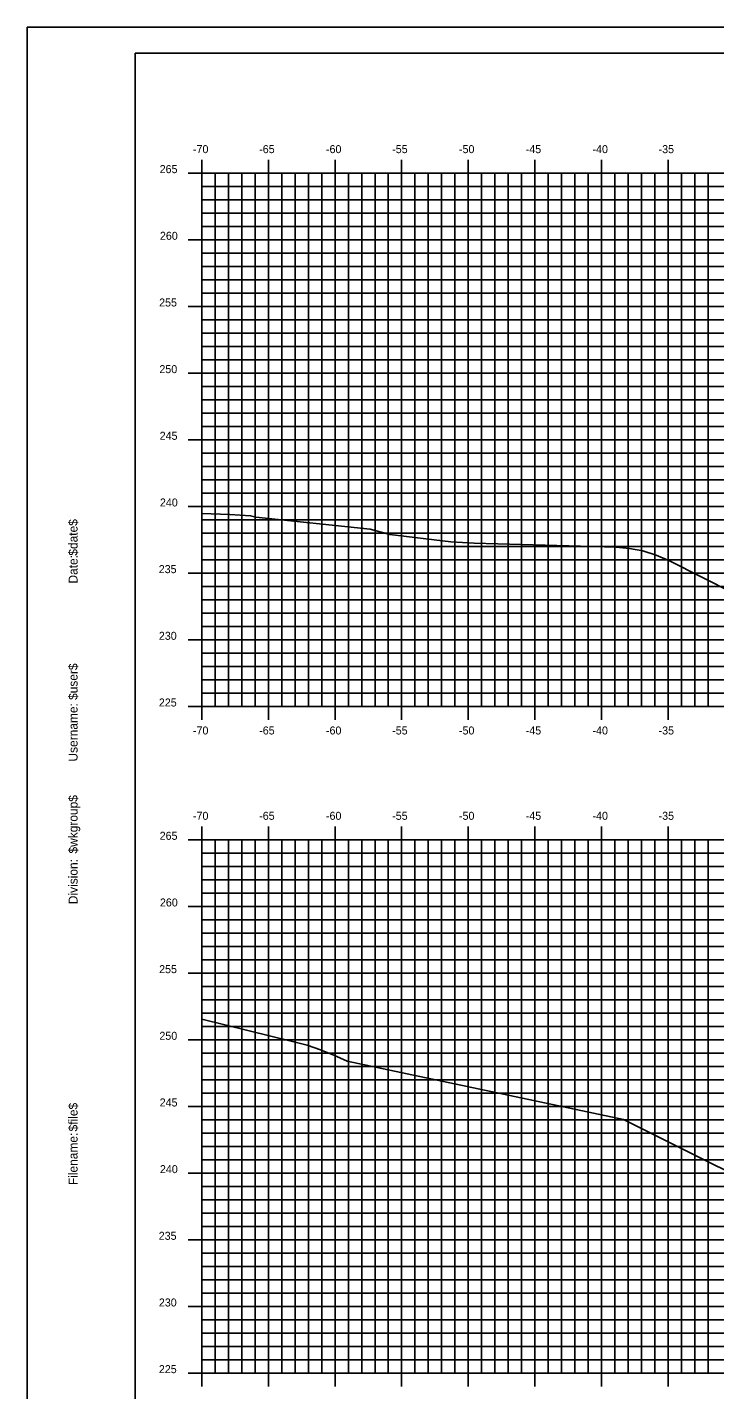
# Model space of a CAD drawing. Extents: x 1168600 to 1177589, y 610178 to 611246.
# Drawn here: x 1174091.5 to 1174143.1, y 610276.6 to 610378.7 of the extents above; entities that cross this region are included whole.
import ezdxf

# ---------------------------------------------------------------- set-up
doc = ezdxf.new("R2010")
doc.units = 0
for name, color, linetype in [('_Station Equation', 7, 'Continuous'), ('BORDER', 7, 'Continuous'), ('H_V ANNOTATION', 7, 'Continuous'), ('MAJOR', 7, 'Continuous'), ('MINOR', 7, 'Continuous'), ('PLOT BOUNDARY', 7, 'Continuous')]:
    doc.layers.add(name, color=color, linetype=linetype)

msp = doc.modelspace()

# ---------------------------------------------------------------- linework, layer by layer
at = {"layer": '_Station Equation'}
for points in [[(1174104.58, 610342.27), (1174106.68, 610342.2), (1174108.24, 610342.1), (1174108.63, 610342), (1174117.22, 610341.1), (1174118.7, 610340.71), (1174123.26, 610340.14), (1174125.03, 610340.05), (1174135.67, 610339.74), (1174135.67, 610339.74), (1174135.67, 610339.74), (1174136.67, 610339.66), (1174137.67, 610339.47), (1174138.67, 610339.15), (1174139.67, 610338.72), (1174139.67, 610338.72), (1174144.49, 610336.31), (1174144.49, 610336.31)], [(1174104.58, 610304.35), (1174111.49, 610302.66), (1174111.49, 610302.66), (1174111.49, 610302.66), (1174112.49, 610302.39), (1174113.49, 610302.06), (1174114.49, 610301.66), (1174115.49, 610301.19), (1174136.23, 610296.83), (1174136.23, 610296.83), (1174136.23, 610296.83), (1174150.5, 610289.69)]]:
    msp.add_lwpolyline(points, dxfattribs=at)
at = {"layer": 'BORDER'}
for p, q in [((1174259.58, 610376.8), (1174099.58, 610376.8)), ((1174099.58, 610376.8), (1174099.58, 610271.8))]:
    msp.add_line(p, q, dxfattribs=at)
at = {"layer": 'MAJOR'}
for p, q in [((1174104.58, 610368.8), (1174104.58, 610367.8)), ((1174109.58, 610368.8), (1174109.58, 610367.8)), ((1174114.58, 610368.8), (1174114.58, 610367.8)), ((1174119.58, 610368.8), (1174119.58, 610367.8)), ((1174124.58, 610368.8), (1174124.58, 610367.8)), ((1174129.58, 610368.8), (1174129.58, 610367.8)), ((1174134.58, 610368.8), (1174134.58, 610367.8)), ((1174139.58, 610368.8), (1174139.58, 610367.8)), ((1174103.57, 610367.8), (1174104.58, 610367.8)), ((1174104.58, 610367.8), (1174244.58, 610367.8)), ((1174104.58, 610327.8), (1174104.58, 610367.8)), ((1174104.58, 610327.8), (1174104.58, 610367.8)), ((1174104.58, 610367.8), (1174244.58, 610367.8)), ((1174109.58, 610327.8), (1174109.58, 610367.8)), ((1174114.58, 610327.8), (1174114.58, 610367.8)), ((1174119.58, 610327.8), (1174119.58, 610367.8)), ((1174124.58, 610327.8), (1174124.58, 610367.8)), ((1174129.58, 610327.8), (1174129.58, 610367.8)), ((1174134.58, 610327.8), (1174134.58, 610367.8)), ((1174139.58, 610327.8), (1174139.58, 610367.8)), ((1174103.57, 610362.8), (1174104.58, 610362.8)), ((1174104.58, 610362.8), (1174244.58, 610362.8)), ((1174103.57, 610357.8), (1174104.58, 610357.8)), ((1174104.58, 610357.8), (1174244.58, 610357.8)), ((1174103.57, 610352.8), (1174104.58, 610352.8)), ((1174104.58, 610352.8), (1174244.58, 610352.8)), ((1174103.57, 610347.8), (1174104.58, 610347.8)), ((1174104.58, 610347.8), (1174244.58, 610347.8)), ((1174103.57, 610342.8), (1174104.58, 610342.8)), ((1174104.58, 610342.8), (1174244.58, 610342.8)), ((1174103.57, 610337.8), (1174104.58, 610337.8)), ((1174104.58, 610337.8), (1174244.58, 610337.8)), ((1174103.57, 610332.8), (1174104.58, 610332.8)), ((1174104.58, 610332.8), (1174244.58, 610332.8)), ((1174103.57, 610327.8), (1174104.58, 610327.8)), ((1174104.58, 610327.8), (1174244.58, 610327.8)), ((1174104.58, 610327.8), (1174244.58, 610327.8)), ((1174104.58, 610326.8), (1174104.58, 610327.8)), ((1174109.58, 610326.8), (1174109.58, 610327.8)), ((1174114.58, 610326.8), (1174114.58, 610327.8)), ((1174119.58, 610326.8), (1174119.58, 610327.8)), ((1174124.58, 610326.8), (1174124.58, 610327.8)), ((1174129.58, 610326.8), (1174129.58, 610327.8)), ((1174134.58, 610326.8), (1174134.58, 610327.8)), ((1174139.58, 610326.8), (1174139.58, 610327.8)), ((1174104.58, 610318.8), (1174104.58, 610317.8)), ((1174109.58, 610318.8), (1174109.58, 610317.8)), ((1174114.58, 610318.8), (1174114.58, 610317.8)), ((1174119.58, 610318.8), (1174119.58, 610317.8)), ((1174124.58, 610318.8), (1174124.58, 610317.8)), ((1174129.58, 610318.8), (1174129.58, 610317.8)), ((1174134.58, 610318.8), (1174134.58, 610317.8)), ((1174139.58, 610318.8), (1174139.58, 610317.8)), ((1174103.57, 610317.8), (1174104.58, 610317.8)), ((1174104.58, 610317.8), (1174244.58, 610317.8)), ((1174104.58, 610277.8), (1174104.58, 610317.8)), ((1174104.58, 610277.8), (1174104.58, 610317.8)), ((1174104.58, 610317.8), (1174244.58, 610317.8)), ((1174109.58, 610277.8), (1174109.58, 610317.8)), ((1174114.58, 610277.8), (1174114.58, 610317.8)), ((1174119.58, 610277.8), (1174119.58, 610317.8)), ((1174124.58, 610277.8), (1174124.58, 610317.8)), ((1174129.58, 610277.8), (1174129.58, 610317.8)), ((1174134.58, 610277.8), (1174134.58, 610317.8)), ((1174139.58, 610277.8), (1174139.58, 610317.8)), ((1174103.57, 610312.8), (1174104.58, 610312.8)), ((1174104.58, 610312.8), (1174244.58, 610312.8)), ((1174103.57, 610307.8), (1174104.58, 610307.8)), ((1174104.58, 610307.8), (1174244.58, 610307.8)), ((1174103.57, 610302.8), (1174104.58, 610302.8)), ((1174104.58, 610302.8), (1174244.58, 610302.8)), ((1174103.57, 610297.8), (1174104.58, 610297.8)), ((1174104.58, 610297.8), (1174244.58, 610297.8)), ((1174103.57, 610292.8), (1174104.58, 610292.8)), ((1174104.58, 610292.8), (1174244.58, 610292.8)), ((1174103.57, 610287.8), (1174104.58, 610287.8)), ((1174104.58, 610287.8), (1174244.58, 610287.8)), ((1174103.57, 610282.8), (1174104.58, 610282.8)), ((1174104.58, 610282.8), (1174244.58, 610282.8)), ((1174103.57, 610277.8), (1174104.58, 610277.8)), ((1174104.58, 610277.8), (1174244.58, 610277.8)), ((1174104.58, 610277.8), (1174244.58, 610277.8)), ((1174104.58, 610276.8), (1174104.58, 610277.8)), ((1174109.58, 610276.8), (1174109.58, 610277.8)), ((1174114.58, 610276.8), (1174114.58, 610277.8)), ((1174119.58, 610276.8), (1174119.58, 610277.8)), ((1174124.58, 610276.8), (1174124.58, 610277.8)), ((1174129.58, 610276.8), (1174129.58, 610277.8)), ((1174134.58, 610276.8), (1174134.58, 610277.8)), ((1174139.58, 610276.8), (1174139.58, 610277.8))]:
    msp.add_line(p, q, dxfattribs=at)
at = {"layer": 'MINOR'}
for p, q in [((1174105.58, 610327.8), (1174105.58, 610367.8)), ((1174106.58, 610327.8), (1174106.58, 610367.8)), ((1174107.58, 610327.8), (1174107.58, 610367.8)), ((1174108.58, 610327.8), (1174108.58, 610367.8)), ((1174110.58, 610327.8), (1174110.58, 610367.8)), ((1174111.58, 610327.8), (1174111.58, 610367.8)), ((1174112.58, 610327.8), (1174112.58, 610367.8)), ((1174113.58, 610327.8), (1174113.58, 610367.8)), ((1174115.58, 610327.8), (1174115.58, 610367.8)), ((1174116.58, 610327.8), (1174116.58, 610367.8)), ((1174117.58, 610327.8), (1174117.58, 610367.8)), ((1174118.58, 610327.8), (1174118.58, 610367.8)), ((1174120.58, 610327.8), (1174120.58, 610367.8)), ((1174121.58, 610327.8), (1174121.58, 610367.8)), ((1174122.58, 610327.8), (1174122.58, 610367.8)), ((1174123.58, 610327.8), (1174123.58, 610367.8)), ((1174125.58, 610327.8), (1174125.58, 610367.8)), ((1174126.58, 610327.8), (1174126.58, 610367.8)), ((1174127.58, 610327.8), (1174127.58, 610367.8)), ((1174128.58, 610327.8), (1174128.58, 610367.8)), ((1174130.58, 610327.8), (1174130.58, 610367.8)), ((1174131.58, 610327.8), (1174131.58, 610367.8)), ((1174132.58, 610327.8), (1174132.58, 610367.8)), ((1174133.58, 610327.8), (1174133.58, 610367.8)), ((1174135.58, 610327.8), (1174135.58, 610367.8)), ((1174136.58, 610327.8), (1174136.58, 610367.8)), ((1174137.58, 610327.8), (1174137.58, 610367.8)), ((1174138.58, 610327.8), (1174138.58, 610367.8)), ((1174140.58, 610327.8), (1174140.58, 610367.8)), ((1174141.58, 610327.8), (1174141.58, 610367.8)), ((1174142.58, 610327.8), (1174142.58, 610367.8)), ((1174104.58, 610366.8), (1174244.58, 610366.8)), ((1174104.58, 610366.8), (1174105.58, 610366.8)), ((1174104.58, 610365.8), (1174244.58, 610365.8)), ((1174104.58, 610365.8), (1174105.58, 610365.8)), ((1174104.58, 610364.8), (1174244.58, 610364.8)), ((1174104.58, 610364.8), (1174105.58, 610364.8)), ((1174104.58, 610363.8), (1174244.58, 610363.8)), ((1174104.58, 610363.8), (1174105.58, 610363.8)), ((1174104.58, 610361.8), (1174244.58, 610361.8)), ((1174104.58, 610361.8), (1174105.58, 610361.8)), ((1174104.58, 610360.8), (1174244.58, 610360.8)), ((1174104.58, 610360.8), (1174105.58, 610360.8)), ((1174104.58, 610359.8), (1174244.58, 610359.8)), ((1174104.58, 610359.8), (1174105.58, 610359.8)), ((1174104.58, 610358.8), (1174244.58, 610358.8)), ((1174104.58, 610358.8), (1174105.58, 610358.8)), ((1174104.58, 610356.8), (1174244.58, 610356.8)), ((1174104.58, 610356.8), (1174105.58, 610356.8)), ((1174104.58, 610355.8), (1174244.58, 610355.8)), ((1174104.58, 610355.8), (1174105.58, 610355.8)), ((1174104.58, 610354.8), (1174244.58, 610354.8)), ((1174104.58, 610354.8), (1174105.58, 610354.8)), ((1174104.58, 610353.8), (1174244.58, 610353.8)), ((1174104.58, 610353.8), (1174105.58, 610353.8)), ((1174104.58, 610351.8), (1174244.58, 610351.8)), ((1174104.58, 610351.8), (1174105.58, 610351.8)), ((1174104.58, 610350.8), (1174244.58, 610350.8)), ((1174104.58, 610350.8), (1174105.58, 610350.8)), ((1174104.58, 610349.8), (1174244.58, 610349.8)), ((1174104.58, 610349.8), (1174105.58, 610349.8)), ((1174104.58, 610348.8), (1174244.58, 610348.8)), ((1174104.58, 610348.8), (1174105.58, 610348.8)), ((1174104.58, 610346.8), (1174244.58, 610346.8)), ((1174104.58, 610346.8), (1174105.58, 610346.8)), ((1174104.58, 610345.8), (1174244.58, 610345.8)), ((1174104.58, 610345.8), (1174105.58, 610345.8)), ((1174104.58, 610344.8), (1174244.58, 610344.8)), ((1174104.58, 610344.8), (1174105.58, 610344.8)), ((1174104.58, 610343.8), (1174244.58, 610343.8)), ((1174104.58, 610343.8), (1174105.58, 610343.8)), ((1174104.58, 610341.8), (1174244.58, 610341.8)), ((1174104.58, 610341.8), (1174105.58, 610341.8)), ((1174104.58, 610340.8), (1174244.58, 610340.8)), ((1174104.58, 610340.8), (1174105.58, 610340.8)), ((1174104.58, 610339.8), (1174244.58, 610339.8)), ((1174104.58, 610339.8), (1174105.58, 610339.8)), ((1174104.58, 610338.8), (1174244.58, 610338.8)), ((1174104.58, 610338.8), (1174105.58, 610338.8)), ((1174104.58, 610336.8), (1174244.58, 610336.8)), ((1174104.58, 610336.8), (1174105.58, 610336.8)), ((1174104.58, 610335.8), (1174244.58, 610335.8)), ((1174104.58, 610335.8), (1174105.58, 610335.8)), ((1174104.58, 610334.8), (1174244.58, 610334.8)), ((1174104.58, 610334.8), (1174105.58, 610334.8)), ((1174104.58, 610333.8), (1174244.58, 610333.8)), ((1174104.58, 610333.8), (1174105.58, 610333.8)), ((1174104.58, 610331.8), (1174244.58, 610331.8)), ((1174104.58, 610331.8), (1174105.58, 610331.8)), ((1174104.58, 610330.8), (1174244.58, 610330.8)), ((1174104.58, 610330.8), (1174105.58, 610330.8)), ((1174104.58, 610329.8), (1174244.58, 610329.8)), ((1174104.58, 610329.8), (1174105.58, 610329.8)), ((1174104.58, 610328.8), (1174244.58, 610328.8)), ((1174104.58, 610328.8), (1174105.58, 610328.8)), ((1174105.58, 610277.8), (1174105.58, 610317.8)), ((1174106.58, 610277.8), (1174106.58, 610317.8)), ((1174107.58, 610277.8), (1174107.58, 610317.8)), ((1174108.58, 610277.8), (1174108.58, 610317.8)), ((1174110.58, 610277.8), (1174110.58, 610317.8)), ((1174111.58, 610277.8), (1174111.58, 610317.8)), ((1174112.58, 610277.8), (1174112.58, 610317.8)), ((1174113.58, 610277.8), (1174113.58, 610317.8)), ((1174115.58, 610277.8), (1174115.58, 610317.8)), ((1174116.58, 610277.8), (1174116.58, 610317.8)), ((1174117.58, 610277.8), (1174117.58, 610317.8)), ((1174118.58, 610277.8), (1174118.58, 610317.8)), ((1174120.58, 610277.8), (1174120.58, 610317.8)), ((1174121.58, 610277.8), (1174121.58, 610317.8)), ((1174122.58, 610277.8), (1174122.58, 610317.8)), ((1174123.58, 610277.8), (1174123.58, 610317.8)), ((1174125.58, 610277.8), (1174125.58, 610317.8)), ((1174126.58, 610277.8), (1174126.58, 610317.8)), ((1174127.58, 610277.8), (1174127.58, 610317.8)), ((1174128.58, 610277.8), (1174128.58, 610317.8)), ((1174130.58, 610277.8), (1174130.58, 610317.8)), ((1174131.58, 610277.8), (1174131.58, 610317.8)), ((1174132.58, 610277.8), (1174132.58, 610317.8)), ((1174133.58, 610277.8), (1174133.58, 610317.8)), ((1174135.58, 610277.8), (1174135.58, 610317.8)), ((1174136.58, 610277.8), (1174136.58, 610317.8)), ((1174137.58, 610277.8), (1174137.58, 610317.8)), ((1174138.58, 610277.8), (1174138.58, 610317.8)), ((1174140.58, 610277.8), (1174140.58, 610317.8)), ((1174141.58, 610277.8), (1174141.58, 610317.8)), ((1174142.58, 610277.8), (1174142.58, 610317.8)), ((1174104.58, 610316.8), (1174244.58, 610316.8)), ((1174104.58, 610316.8), (1174105.58, 610316.8)), ((1174104.58, 610315.8), (1174244.58, 610315.8)), ((1174104.58, 610315.8), (1174105.58, 610315.8)), ((1174104.58, 610314.8), (1174244.58, 610314.8)), ((1174104.58, 610314.8), (1174105.58, 610314.8)), ((1174104.58, 610313.8), (1174244.58, 610313.8)), ((1174104.58, 610313.8), (1174105.58, 610313.8)), ((1174104.58, 610311.8), (1174244.58, 610311.8)), ((1174104.58, 610311.8), (1174105.58, 610311.8)), ((1174104.58, 610310.8), (1174244.58, 610310.8)), ((1174104.58, 610310.8), (1174105.58, 610310.8)), ((1174104.58, 610309.8), (1174244.58, 610309.8)), ((1174104.58, 610309.8), (1174105.58, 610309.8)), ((1174104.58, 610308.8), (1174244.58, 610308.8)), ((1174104.58, 610308.8), (1174105.58, 610308.8)), ((1174104.58, 610306.8), (1174244.58, 610306.8)), ((1174104.58, 610306.8), (1174105.58, 610306.8)), ((1174104.58, 610305.8), (1174244.58, 610305.8)), ((1174104.58, 610305.8), (1174105.58, 610305.8)), ((1174104.58, 610304.8), (1174244.58, 610304.8)), ((1174104.58, 610304.8), (1174105.58, 610304.8)), ((1174104.58, 610303.8), (1174244.58, 610303.8)), ((1174104.58, 610303.8), (1174105.58, 610303.8)), ((1174104.58, 610301.8), (1174244.58, 610301.8)), ((1174104.58, 610301.8), (1174105.58, 610301.8)), ((1174104.58, 610300.8), (1174244.58, 610300.8)), ((1174104.58, 610300.8), (1174105.58, 610300.8)), ((1174104.58, 610299.8), (1174244.58, 610299.8)), ((1174104.58, 610299.8), (1174105.58, 610299.8)), ((1174104.58, 610298.8), (1174244.58, 610298.8)), ((1174104.58, 610298.8), (1174105.58, 610298.8)), ((1174104.58, 610296.8), (1174244.58, 610296.8)), ((1174104.58, 610296.8), (1174105.58, 610296.8)), ((1174104.58, 610295.8), (1174244.58, 610295.8)), ((1174104.58, 610295.8), (1174105.58, 610295.8)), ((1174104.58, 610294.8), (1174244.58, 610294.8)), ((1174104.58, 610294.8), (1174105.58, 610294.8)), ((1174104.58, 610293.8), (1174244.58, 610293.8)), ((1174104.58, 610293.8), (1174105.58, 610293.8)), ((1174104.58, 610291.8), (1174244.58, 610291.8)), ((1174104.58, 610291.8), (1174105.58, 610291.8)), ((1174104.58, 610290.8), (1174244.58, 610290.8)), ((1174104.58, 610290.8), (1174105.58, 610290.8)), ((1174104.58, 610289.8), (1174244.58, 610289.8)), ((1174104.58, 610289.8), (1174105.58, 610289.8)), ((1174104.58, 610288.8), (1174244.58, 610288.8)), ((1174104.58, 610288.8), (1174105.58, 610288.8)), ((1174104.58, 610286.8), (1174244.58, 610286.8)), ((1174104.58, 610286.8), (1174105.58, 610286.8)), ((1174104.58, 610285.8), (1174244.58, 610285.8)), ((1174104.58, 610285.8), (1174105.58, 610285.8)), ((1174104.58, 610284.8), (1174244.58, 610284.8)), ((1174104.58, 610284.8), (1174105.58, 610284.8)), ((1174104.58, 610283.8), (1174244.58, 610283.8)), ((1174104.58, 610283.8), (1174105.58, 610283.8)), ((1174104.58, 610281.8), (1174244.58, 610281.8)), ((1174104.58, 610281.8), (1174105.58, 610281.8)), ((1174104.58, 610280.8), (1174244.58, 610280.8)), ((1174104.58, 610280.8), (1174105.58, 610280.8)), ((1174104.58, 610279.8), (1174244.58, 610279.8)), ((1174104.58, 610279.8), (1174105.58, 610279.8)), ((1174104.58, 610278.8), (1174244.58, 610278.8)), ((1174104.58, 610278.8), (1174105.58, 610278.8))]:
    msp.add_line(p, q, dxfattribs=at)
at = {"layer": 'PLOT BOUNDARY'}
msp.add_lwpolyline([(1174091.48, 610268.74), (1174261.48, 610268.74), (1174261.48, 610378.74), (1174091.48, 610378.74)], close=True, dxfattribs=at)

# ---------------------------------------------------------------- texts
at = {"layer": 'BORDER'}
for s, p in [('$date$', (1174095.26, 610339.11)), ('Date:', (1174095.26, 610337.02)), ('$user$', (1174095.26, 610328.29)), ('Username:', (1174095.26, 610323.67)), ('$wkgroup$', (1174095.26, 610316.77)), ('Division:', (1174095.26, 610312.97)), ('$file$', (1174095.26, 610295.93)), ('Filename:', (1174095.26, 610291.9))]:
    msp.add_text(s, height=0.67, rotation=90, dxfattribs=at).set_placement(p)
at = {"layer": 'H_V ANNOTATION'}
for s, p in [('-70', (1174103.92, 610369.3)), ('-65', (1174108.89, 610369.3)), ('-60', (1174113.9, 610369.3)), ('-55', (1174118.87, 610369.3)), ('-50', (1174123.88, 610369.3)), ('-45', (1174128.89, 610369.3)), ('-40', (1174133.9, 610369.3)), ('-35', (1174138.86, 610369.3)), ('265', (1174101.42, 610367.8)), ('260', (1174101.44, 610362.8)), ('255', (1174101.38, 610357.8)), ('250', (1174101.4, 610352.8)), ('245', (1174101.42, 610347.8)), ('240', (1174101.44, 610342.8)), ('235', (1174101.35, 610337.8)), ('230', (1174101.36, 610332.8)), ('225', (1174101.36, 610327.8)), ('-70', (1174103.92, 610325.7)), ('-65', (1174108.89, 610325.7)), ('-60', (1174113.9, 610325.7)), ('-55', (1174118.87, 610325.7)), ('-50', (1174123.88, 610325.7)), ('-45', (1174128.89, 610325.7)), ('-40', (1174133.9, 610325.7)), ('-35', (1174138.86, 610325.7)), ('-70', (1174103.92, 610319.3)), ('-65', (1174108.89, 610319.3)), ('-60', (1174113.9, 610319.3)), ('-55', (1174118.87, 610319.3)), ('-50', (1174123.88, 610319.3)), ('-45', (1174128.89, 610319.3)), ('-40', (1174133.9, 610319.3)), ('-35', (1174138.86, 610319.3)), ('265', (1174101.42, 610317.8)), ('260', (1174101.44, 610312.8)), ('255', (1174101.38, 610307.8)), ('250', (1174101.4, 610302.8)), ('245', (1174101.42, 610297.8)), ('240', (1174101.44, 610292.8)), ('235', (1174101.35, 610287.8)), ('230', (1174101.36, 610282.8)), ('225', (1174101.36, 610277.8))]:
    msp.add_text(s, height=0.6, dxfattribs=at).set_placement(p)

doc.saveas('drawing.dxf')
